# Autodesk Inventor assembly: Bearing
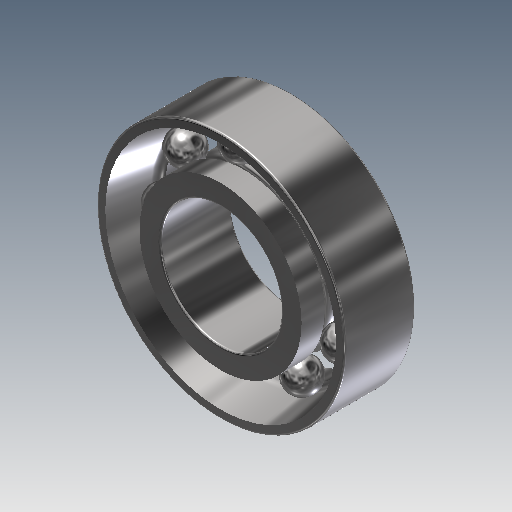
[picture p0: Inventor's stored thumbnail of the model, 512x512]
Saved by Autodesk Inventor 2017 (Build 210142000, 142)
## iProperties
ClientObjectVersion: 1
Created: 2019-02
Part Number: Bearing
Document SubType Name: Assembly
Designer: user
Author: user
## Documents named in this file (2)
- C:\Users\user\Desktop\Ensamble reductor de velocidad\Ensamble\Design Accelerator\Bearing1.iam
- C:\Users\user\Documents\Inventor\Content Center Files\R2017\en-US\BS 292 (II)\BS 292_ Part 1 - 7003 - 17 x 35 x 10.ipt
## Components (1 placed, 1 different names)
1. BS 292: Part 1 (II) - Metric 7003 - 17 x 35 x 10:1
